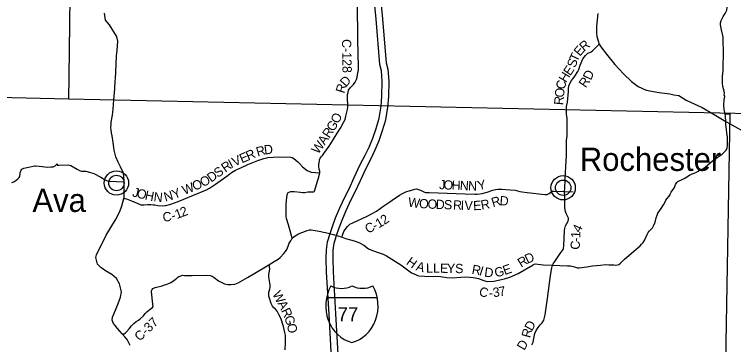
# Model space of a CAD drawing. Extents: x -452339 to 6403467, y -1 to 1814750.
# Drawn here: x -67891 to -44654, y 1614709 to 1625369 of the extents above; entities that cross this region are included whole.
import ezdxf

# ---------------------------------------------------------------- set-up
doc = ezdxf.new("R2010")
doc.units = 0
for name, color, linetype in [('Default', 7, 'Continuous'), ('GM_X_Adjacent_County_Text', 7, 'Continuous'), ('GM_X_County', 7, 'Continuous'), ('GM_X_County_Road', 7, 'Continuous'), ('GM_X_County_Road_Text', 7, 'Continuous'), ('GM_X_Minor_Lake_Text', 7, 'Continuous'), ('GM_X_Section', 7, 'Continuous'), ('GM_X_Section_Text', 7, 'Continuous')]:
    doc.layers.add(name, color=color, linetype=linetype)

msp = doc.modelspace()

# ---------------------------------------------------------------- linework, layer by layer
at = {"layer": 'Default'}
for points in [[(-44955, 1622772), (-44956, 1622773), (-44951, 1622812), (-44961, 1622892), (-45003, 1623040), (-45017, 1623148), (-45009, 1623362), (-44991, 1623560), (-44986, 1623652), (-44982, 1624125), (-44988, 1624557), (-44996, 1624632), (-45048, 1624874), (-45073, 1625030), (-45073, 1625094), (-45059, 1625168), (-44987, 1625298), (-44923, 1625398), (-44877, 1625509), (-44847, 1625681), (-44827, 1626210)], [(-57119, 1622389), (-57116, 1622414), (-57125, 1622681), (-57124, 1622783), (-57107, 1622852), (-57099, 1622922), (-57038, 1622996), (-56930, 1623111), (-56881, 1623182), (-56840, 1623266), (-56820, 1623340), (-56791, 1623497), (-56778, 1623571), (-56772, 1623669), (-56795, 1624548), (-56800, 1625047), (-56805, 1625229), (-56810, 1625638)], [(-64710, 1622221), (-64703, 1622311), (-64678, 1622608), (-64651, 1622967), (-64635, 1623240), (-64628, 1623282), (-64591, 1624018), (-64580, 1624127), (-64574, 1624200), (-64560, 1624367), (-64552, 1624506), (-64571, 1624602), (-64593, 1624670), (-64817, 1625031), (-64948, 1625185), (-64981, 1625410)], [(-44910, 1621913), (-44917, 1622075), (-44930, 1622159), (-44960, 1622300), (-44975, 1622441), (-44958, 1622608), (-44937, 1622721), (-44955, 1622772)], [(-64445, 1619124), (-64420, 1619187), (-64358, 1619423), (-64349, 1619456), (-64345, 1619969), (-64353, 1620155), (-64363, 1620207), (-64374, 1620267), (-64458, 1620446), (-64469, 1620467), (-64540, 1620598), (-64611, 1620768), (-64662, 1620990), (-64703, 1621237), (-64735, 1621445), (-64752, 1621549), (-64764, 1621643), (-64773, 1621712), (-64767, 1621844), (-64761, 1621889), (-64717, 1622119), (-64710, 1622221)], [(-58079, 1620051), (-58079, 1620053), (-58026, 1620254), (-58026, 1620305), (-58043, 1620369), (-58053, 1620455), (-58050, 1620535), (-58036, 1620631), (-58031, 1620679), (-58015, 1620723), (-57983, 1620770), (-57934, 1620818), (-57888, 1620877), (-57724, 1621120), (-57558, 1621378), (-57441, 1621563), (-57333, 1621732), (-57301, 1621804), (-57209, 1621977), (-57178, 1622085), (-57131, 1622303), (-57119, 1622389)], [(-50504, 1617270), (-50486, 1617312), (-50406, 1617428), (-50255, 1617655), (-50165, 1617779), (-50151, 1617807), (-50141, 1617893), (-50121, 1618390), (-50111, 1618456), (-50082, 1618547), (-50000, 1618699), (-49992, 1618749), (-49988, 1618795), (-50008, 1618837), (-50064, 1618943), (-50084, 1619001), (-50104, 1619123), (-50108, 1619514), (-50116, 1619650), (-50109, 1619762), (-50087, 1620261), (-50073, 1620455), (-50057, 1620810), (-50056, 1621302), (-50031, 1621453), (-50028, 1621951), (-50031, 1622021), (-50039, 1622078), (-50052, 1622160)], [(-44889, 1621651), (-44908, 1621811), (-44910, 1621913)], [(-50504, 1617270), (-50266, 1617262), (-50018, 1617253), (-49922, 1617247), (-49842, 1617231), (-49760, 1617205), (-49700, 1617189), (-49640, 1617187), (-49401, 1617222), (-49209, 1617256), (-48955, 1617276), (-48797, 1617291), (-48681, 1617289), (-48521, 1617285), (-48461, 1617277), (-48407, 1617283), (-48363, 1617297), (-48303, 1617333), (-48175, 1617462), (-48035, 1617590), (-47882, 1617729), (-47674, 1617899), (-47626, 1617949), (-47572, 1618010), (-47526, 1618090), (-47452, 1618260), (-47430, 1618304), (-47412, 1618332), (-47378, 1618372), (-47314, 1618433), (-47276, 1618477), (-47231, 1618563), (-47187, 1618661), (-47153, 1618803), (-47129, 1618889), (-47103, 1618952), (-46999, 1619100), (-46923, 1619222), (-46869, 1619316), (-46843, 1619369), (-46803, 1619423), (-46744, 1619487), (-46708, 1619539), (-46706, 1619567), (-46676, 1619633), (-46584, 1619751), (-46566, 1619785), (-46528, 1619880), (-46484, 1619942), (-46446, 1619984), (-46362, 1620022), (-46254, 1620076), (-46196, 1620102), (-46078, 1620175), (-45996, 1620219), (-45930, 1620247), (-45870, 1620269), (-45799, 1620307), (-45753, 1620335), (-45679, 1620370), (-45631, 1620394), (-45567, 1620450), (-45351, 1620630), (-45189, 1620751), (-45025, 1620861), (-44943, 1620927), (-44907, 1620975), (-44864, 1621052), (-44854, 1621153), (-44849, 1621264), (-44849, 1621406), (-44877, 1621550), (-44889, 1621651)], [(-64358, 1619423), (-64311, 1619426), (-64267, 1619416), (-64106, 1619348), (-63924, 1619272), (-63804, 1619223), (-63754, 1619218), (-63696, 1619220), (-63592, 1619233), (-63536, 1619237), (-63482, 1619230), (-63412, 1619222), (-63354, 1619217), (-63252, 1619204), (-63118, 1619191), (-62998, 1619200), (-62840, 1619239), (-62597, 1619329), (-62101, 1619535), (-61688, 1619703), (-61589, 1619756), (-61398, 1619891), (-60980, 1620183), (-60874, 1620268), (-60749, 1620343), (-60556, 1620427), (-60347, 1620523), (-60026, 1620657), (-59828, 1620719), (-59698, 1620750), (-59361, 1620767), (-58957, 1620762), (-58921, 1620752), (-58865, 1620717), (-58730, 1620607), (-58678, 1620558), (-58583, 1620450), (-58432, 1620331), (-58302, 1620280), (-58026, 1620254)], [(-67970, 1619938), (-67891, 1619977), (-67780, 1620063), (-67741, 1620104), (-67720, 1620141), (-67704, 1620257), (-67677, 1620336), (-67646, 1620376), (-67584, 1620407), (-67433, 1620436), (-67231, 1620480), (-67200, 1620484), (-67095, 1620470), (-66811, 1620439), (-66713, 1620443), (-66643, 1620450), (-66571, 1620476), (-66507, 1620545), (-66508, 1620501), (-66452, 1620506), (-66152, 1620511), (-66114, 1620502), (-66068, 1620489), (-65866, 1620368), (-65791, 1620327), (-65724, 1620306), (-65654, 1620306), (-65585, 1620307), (-65466, 1620275), (-65319, 1620232), (-65101, 1620111), (-64956, 1620024), (-64911, 1620002), (-64854, 1619990), (-64817, 1619982), (-64597, 1619976), (-64345, 1619969)], [(-58912, 1618142), (-58951, 1618264), (-59039, 1618576), (-59095, 1618780), (-59111, 1618848), (-59114, 1618966), (-59106, 1619234), (-59094, 1619465), (-59070, 1619579), (-59045, 1619619), (-58997, 1619644), (-58957, 1619652), (-58857, 1619649), (-58643, 1619627), (-58575, 1619619), (-58505, 1619618), (-58405, 1619637), (-58355, 1619641), (-58267, 1619642), (-58227, 1619638), (-58215, 1619644), (-58197, 1619664), (-58088, 1620018), (-58079, 1620051)], [(-57301, 1618173), (-57289, 1618244), (-57243, 1618363), (-57208, 1618428), (-57125, 1618523), (-57049, 1618593), (-56960, 1618644), (-56495, 1618853), (-56313, 1618947), (-56188, 1619021), (-55955, 1619184), (-55764, 1619319), (-55683, 1619377), (-55447, 1619535), (-55354, 1619591), (-55239, 1619645), (-55100, 1619685), (-55088, 1619689)], [(-55088, 1619689), (-54951, 1619729), (-54901, 1619735), (-54865, 1619732), (-54774, 1619692), (-54645, 1619632), (-54609, 1619621), (-54489, 1619619), (-53324, 1619572), (-53010, 1619561), (-52936, 1619567), (-52775, 1619590), (-52619, 1619625), (-52435, 1619698), (-52351, 1619720), (-52275, 1619729), (-52143, 1619729), (-51871, 1619710), (-51707, 1619691), (-51556, 1619656), (-51484, 1619637), (-51325, 1619622), (-50748, 1619558), (-50682, 1619559), (-50617, 1619587), (-50550, 1619638), (-50518, 1619658), (-50452, 1619666), (-50116, 1619650)], [(-50116, 1619650), (-49840, 1619637)], [(-64151, 1614677), (-64245, 1614869), (-64319, 1614963), (-64404, 1615054), (-64555, 1615229), (-64640, 1615321), (-64684, 1615394), (-64729, 1615496), (-64719, 1615594), (-64628, 1615819), (-64541, 1616040), (-64467, 1616241), (-64432, 1616416), (-64491, 1616672), (-64588, 1616838), (-64738, 1616970), (-64943, 1617087), (-65094, 1617195), (-65209, 1617304), (-65255, 1617516), (-65235, 1617612), (-64928, 1618240), (-64623, 1618735), (-64500, 1618982), (-64445, 1619124)], [(-64404, 1615054), (-64349, 1615057), (-64313, 1615081), (-64275, 1615107), (-64182, 1615216), (-64108, 1615310), (-64036, 1615388), (-63956, 1615456), (-63884, 1615503), (-63826, 1615539), (-63720, 1615639), (-63664, 1615711), (-63610, 1615767), (-63500, 1615852), (-63426, 1615910), (-63408, 1615940), (-63413, 1616014), (-63465, 1616411), (-63459, 1616449), (-63445, 1616487), (-63417, 1616521), (-63343, 1616553), (-63117, 1616609), (-63039, 1616634), (-62985, 1616650), (-62929, 1616674), (-62835, 1616714), (-62755, 1616764), (-62683, 1616818), (-62654, 1616848), (-62614, 1616887), (-62574, 1616911), (-62482, 1616943), (-62450, 1616951), (-62396, 1616945), (-62316, 1616941), (-62144, 1616941), (-61698, 1616946), (-61570, 1616936), (-61502, 1616920), (-61434, 1616878), (-61298, 1616768), (-61102, 1616675), (-61000, 1616653), (-60898, 1616647), (-60768, 1616665), (-60662, 1616699), (-60356, 1616878), (-59837, 1617191), (-59669, 1617288), (-59497, 1617388), (-59371, 1617464), (-59299, 1617521), (-59181, 1617653), (-59132, 1617719), (-59094, 1617775), (-59050, 1617888), (-59008, 1617986), (-58962, 1618062), (-58912, 1618142), (-58860, 1618186), (-58820, 1618222), (-58712, 1618281), (-58430, 1618397), (-58356, 1618419), (-58302, 1618418), (-58044, 1618370), (-57987, 1618357), (-57987, 1618357)], [(-57987, 1618357), (-57901, 1618338), (-57839, 1618324), (-57585, 1618260), (-57301, 1618173), (-57193, 1618137), (-56917, 1618057), (-56759, 1618005), (-56693, 1617975), (-56621, 1617927), (-56621, 1617927)], [(-56621, 1617927), (-56605, 1617915), (-56447, 1617804), (-56379, 1617766), (-56171, 1617692), (-55979, 1617630), (-55865, 1617574), (-55401, 1617280), (-55056, 1617031), (-54934, 1616967), (-54872, 1616941), (-54828, 1616929), (-54636, 1616919), (-54127, 1616908), (-54063, 1616898), (-53915, 1616876), (-53739, 1616866), (-53465, 1616889), (-53307, 1616897), (-53073, 1616875), (-52999, 1616861), (-52891, 1616838), (-52755, 1616788), (-52661, 1616762), (-52591, 1616748), (-52397, 1616760), (-52055, 1616827), (-51883, 1616883), (-51610, 1617000), (-51132, 1617287), (-51114, 1617295), (-51062, 1617311), (-50804, 1617286), (-50504, 1617270)], [(-59139, 1614540), (-59135, 1614773), (-59135, 1615015), (-59149, 1615103), (-59199, 1615295), (-59286, 1615560), (-59342, 1615684), (-59400, 1615784), (-59456, 1615856), (-59520, 1615906), (-59554, 1615950), (-59596, 1616038), (-59652, 1616204), (-59666, 1616272), (-59674, 1616338), (-59666, 1616400), (-59638, 1616501), (-59630, 1616559), (-59628, 1616625), (-59649, 1616771), (-59671, 1616895), (-59673, 1616927), (-59667, 1616977), (-59645, 1617075), (-59635, 1617156), (-59647, 1617230), (-59669, 1617288)], [(-51168, 1614701), (-51134, 1614783), (-51112, 1614903), (-51072, 1615063), (-51030, 1615168), (-50970, 1615258), (-50902, 1615346), (-50834, 1615414), (-50787, 1615501), (-50741, 1615665), (-50665, 1616200), (-50568, 1616945), (-50522, 1617192), (-50504, 1617270)]]:
    msp.add_lwpolyline(points, dxfattribs=at)
for centre, major_axis, start_param, end_param in [((-56741, 1615957), (0, -1211), 4.15077, 6.05619), ((-57324, 1617491), (0, -966), 5.88324, 6.683049), ((-57231, 1615957), (0, -1211), 0.227007, 2.13242), ((-56647, 1617492), (0, -966), 5.883359, 6.683012)]:
    msp.add_ellipse(centre, major_axis=major_axis, ratio=0.9, start_param=start_param, end_param=end_param, dxfattribs=at)
at = {"layer": 'GM_X_County_Road'}
for points in [[(-57598, 1613461), (-57725, 1615691), (-57805, 1617048), (-57817, 1617494), (-57807, 1617773), (-57774, 1618031), (-57690, 1618294), (-57606, 1618550), (-57511, 1618803), (-57376, 1619125), (-57204, 1619490), (-57079, 1619733), (-56912, 1620101), (-56725, 1620504), (-56561, 1620822), (-56430, 1621083), (-56308, 1621376), (-56205, 1621688), (-56103, 1622017), (-56042, 1622403), (-56015, 1622725), (-56007, 1623208), (-56030, 1623550), (-56087, 1623752), (-56201, 1625210), (-56378, 1626980)], [(-57379, 1613474), (-57506, 1615703), (-57585, 1617057), (-57596, 1617493), (-57588, 1617755), (-57559, 1617983), (-57481, 1618226), (-57398, 1618477), (-57306, 1618722), (-57175, 1619036), (-57007, 1619392), (-56881, 1619637), (-56712, 1620009), (-56527, 1620407), (-56365, 1620722), (-56230, 1620992), (-56102, 1621299), (-55996, 1621621), (-55888, 1621967), (-55823, 1622376), (-55795, 1622714), (-55787, 1623214), (-55812, 1623588), (-55870, 1623791), (-55982, 1625230), (-56159, 1626997)], [(-49038, 1625401), (-49087, 1624992), (-49084, 1624768), (-49069, 1624653), (-49033, 1624512), (-48995, 1624411), (-48945, 1624327), (-48761, 1624082), (-48489, 1623750), (-48209, 1623449), (-47954, 1623201), (-47735, 1623038), (-47482, 1622925), (-47055, 1622845), (-46718, 1622806), (-46586, 1622771), (-46429, 1622746), (-46187, 1622602), (-45667, 1622365), (-45340, 1622168), (-44910, 1621913), (-44782, 1621844), (-44177, 1621499)]]:
    msp.add_lwpolyline(points, dxfattribs=at)
at = {"layer": 'GM_X_County_Road_Text'}
for centre, radius in [((-64594, 1619926), 393), ((-64594, 1619926), 249), ((-50161, 1619772), 393), ((-50161, 1619772), 249)]:
    msp.add_circle(centre, radius, dxfattribs=at)
at = {"layer": 'GM_X_Minor_Lake_Text'}
msp.add_line((-57800, 1616229), (-56169, 1616229), dxfattribs=at)
at = {"layer": 'GM_X_Section'}
msp.add_lwpolyline([(-50052, 1622160), (-50053, 1622164), (-50054, 1622248), (-50052, 1622393), (-50022, 1622536), (-49989, 1622884), (-49993, 1622970), (-49975, 1623062), (-49935, 1623159), (-49889, 1623239), (-49838, 1623305), (-49782, 1623373), (-49688, 1623529), (-49652, 1623592), (-49612, 1623734), (-49530, 1623932), (-49440, 1624044), (-49364, 1624113), (-49300, 1624137), (-49254, 1624163), (-49212, 1624195), (-49115, 1624291), (-48995, 1624411)], dxfattribs=at)
at = {"layer": 'GM_X_Section_Text'}
for p, q in [((-66122, 1623362), (-66076, 1626771)), ((-66133, 1622641), (-66122, 1623362)), ((-71381, 1622766), (-66133, 1622641)), ((-66133, 1622641), (-33348, 1621942)), ((-44778, 1622156), (-45205, 1597935)), ((-44930, 1622159), (-44778, 1622156)), ((-44778, 1622156), (-44930, 1622159))]:
    msp.add_line(p, q, dxfattribs=at)

# ---------------------------------------------------------------- texts
at = {"layer": 'Default'}
msp.add_text('77', height=447.7, dxfattribs=at).set_placement((-57449, 1615465))
at = {"layer": 'GM_X_Adjacent_County_Text'}
for s, p in [('Rochester', (-49624, 1620316)), ('Ava', (-67309, 1618992))]:
    msp.add_text(s, height=750, rotation=0, dxfattribs=at).set_placement(p)
at = {"layer": 'GM_X_County'}
for s, rotation, p in [('C-128', 271.1062, (-57309, 1624569)), ('E', 50.0035, (-49620, 1623998)), ('R', 39.7046, (-49485, 1624159)), ('T', 65.0949, (-49703, 1623812)), ('S', 70.4668, (-49768, 1623628)), ('E', 55.5539, (-49933, 1623367)), ('H', 58.8932, (-50067, 1623145)), ('D', 63.867, (-49271, 1623223)), ('D', 48.6523, (-57177, 1623008)), ('C', 77.0893, (-50113, 1622928)), ('R', 55.4038, (-49435, 1622979)), ('R', 72.6895, (-57234, 1622801)), ('O', 84.3006, (-50137, 1622675)), ('R', 84.5197, (-50161, 1622430)), ('O', 64.7446, (-57420, 1621822)), ('G', 57.6471, (-57580, 1621564)), ('R', 56.8631, (-57717, 1621353)), ('W', 54.0288, (-58075, 1620837)), ('A', 56.9167, (-57862, 1621132)), ('R', 16.4499, (-60031, 1620776)), ('D', 7.3713, (-59807, 1620843)), ('V', 24.1777, (-60780, 1620451)), ('E', 23.6966, (-60540, 1620558)), ('R', 23.2503, (-60335, 1620648)), ('R', 35.3725, (-61076, 1620258)), ('I', 27.965, (-60884, 1620395)), ('S', 35.1543, (-61318, 1620086)), ('O', 28.7901, (-61797, 1619787)), ('D', 35.3468, (-61534, 1619934)), ('W', 22.1138, (-62398, 1619540)), ('O', 22.1968, (-62075, 1619671)), ('J', 357.6291, (-54173, 1619726)), ('O', 357.6242, (-54032, 1619720)), ('H', 357.6281, (-53769, 1619709)), ('N', 357.6279, (-53505, 1619698)), ('N', 358.6469, (-53235, 1619687)), ('Y', 12.385, (-52893, 1619689)), ('J', 345.7633, (-64099, 1619498)), ('O', 345.8408, (-63962, 1619464)), ('H', 348.2621, (-63693, 1619396)), ('N', 16.2301, (-63013, 1619320)), ('Y', 22.2968, (-62727, 1619405)), ('N', 353.7904, (-63403, 1619337)), ('W', 353.1752, (-55183, 1619165)), ('R', 16.7635, (-52428, 1619142)), ('D', 355.9567, (-52221, 1619210)), ('O', 355.071, (-54827, 1619122)), ('O', 358.3354, (-54545, 1619099)), ('D', 357.8283, (-54282, 1619091)), ('S', 357.7996, (-54018, 1619081)), ('R', 357.7941, (-53724, 1619070)), ('I', 357.8312, (-53477, 1619060)), ('V', 358.0127, (-53353, 1619055)), ('E', 2.3302, (-53064, 1619046)), ('R', 10.6885, (-52793, 1619061)), ('C', 6.379, (-63085, 1618673)), ('1', 20.7833, (-62643, 1618758)), ('2', 21.5625, (-62466, 1618825)), ('-', 18.0411, (-62775, 1618715)), ('1', 29.6253, (-56121, 1618460)), ('2', 34.5874, (-55936, 1618567)), ('C', 24.8665, (-56479, 1618289)), ('-', 26.8489, (-56245, 1618397)), ('4', 65.4531, (-49609, 1618300)), ('1', 87.9284, (-49609, 1618145)), ('C', 86.0979, (-49631, 1617765)), ('-', 88.0035, (-49613, 1618022)), ('D', 25.5354, (-51315, 1617312)), ('H', 323.8521, (-55255, 1617319)), ('A', 344.4167, (-54936, 1617112)), ('L', 0.8323, (-54589, 1617029)), ('L', 358.8814, (-54367, 1617032)), ('E', 358.8771, (-54143, 1617028)), ('R', 31.271, (-51519, 1617188)), ('Y', 358.8796, (-53919, 1617024)), ('S', 358.8786, (-53655, 1617018)), ('R', 349.9692, (-53129, 1616998)), ('I', 342.2562, (-52896, 1616957)), ('D', 352.6509, (-52721, 1616907)), ('G', 13.2592, (-52342, 1616879)), ('E', 19.7885, (-52049, 1616950)), ('W', 298.1998, (-59565, 1616344)), ('C', 346.1427, (-52899, 1616291)), ('3', 7.5945, (-52415, 1616238)), ('7', 10.961, (-52213, 1616265)), ('-', 5.7938, (-52548, 1616224)), ('A', 298.0656, (-59401, 1616038)), ('R', 294.6307, (-59279, 1615809)), ('C-37', 43.571, (-63842, 1614800)), ('G', 288.458, (-59179, 1615593)), ('D', 60.8601, (-51170, 1615126)), ('O', 284.2103, (-59097, 1615348)), ('R', 74.6904, (-51228, 1614906)), ('D', 59.6092, (-51418, 1614501))]:
    msp.add_text(s, height=300, rotation=rotation, dxfattribs=at).set_placement(p)

doc.saveas('drawing.dxf')
